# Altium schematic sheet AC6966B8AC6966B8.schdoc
size 127 x 101 mm
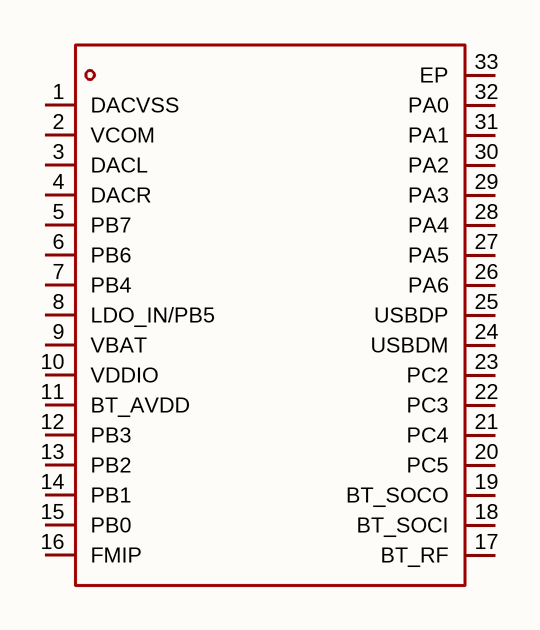
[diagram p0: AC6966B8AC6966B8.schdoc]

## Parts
U?  ac6966b8  [QFN-32_L4.0-W4.0-P0.40-TL-EP2.9]  (value not drawn)

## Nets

Not connected (* = marked no-connect by the designer): U? 1(DACVSS) 2(VCOM) 3(DACL) 4(DACR) 5(PB7) 6(PB6) 7(PB4) 8(LDO_IN/PB5) 9(VBAT) 10(VDDIO) 11(BT_AVDD) 12(PB3) 13(PB2) 14(PB1) 15(PB0) 16(FMIP) 17(BT_RF) 18(BT_SOCI) 19(BT_SOCO) 20(PC5) 21(PC4) 22(PC3) 23(PC2) 24(USBDM) 25(USBDP) 26(PA6) 27(PA5) 28(PA4) 29(PA3) 30(PA2) 31(PA1) 32(PA0) 33(EP)

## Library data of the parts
U? = ac6966b8: CPU内核:-;CPU最大主频:160MHz;CPU位数:32 Bit;; Manufacturer: JL(杰理); AddInBom: yes; ModelId: c3a043996fff46968cb9e2e6abede9b6; ModelName: QFN-32_L4.0-W4.0-H0.8-P0.40-BL-EP2.8; ModelTransform: 157.48,157.48,0,0,0,0,-0.002,0,0; CPU Maximum Speed: 160MHz; Core Size: 32 Bit; ADC (Bit): 16bit；10bit; DAC (Bit): 16bit; Voltage - Supply: 2.2V~5.5V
